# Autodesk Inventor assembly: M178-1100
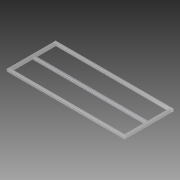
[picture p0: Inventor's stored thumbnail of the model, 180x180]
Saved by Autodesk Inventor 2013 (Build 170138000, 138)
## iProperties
Created: 2004-11
Part Number: M178-1100
Document SubType Name: Assembly
Designer: Autodesk, Inc.
Manufacturer: Standard
Standards Organization: Custom
Description: TABLE, TOP FRAM SUB ASSY
Mass: 12415.3 g
Surface Area: 32169.7 cm^2
Volume: 4521.81 cm^3
Density: 2.74564 g/cm^3
CAGE: 1LJX3
Dept. ID: Product Design
Description #2: ---
Finish #1: ---
Finish #2: ---
Material ID: ---
Project Number: ---
Author: Autodesk, Inc.
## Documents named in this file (6)
- Z:\_DATEN\Test Station\Components\M178-1100.iam
- Z:\_DATEN\Test Station\Components\M178-1002.ipt
- Z:\_DATEN\Test Station\Components\M178-1003.ipt
- Z:\_DATEN\Test Station\Components\20-004.iam
- Z:\_DATEN\Test Station\Components\M178-100_Cross_Phantom.iam
- C:\Users\kelleyb.ADS\Desktop\Samples MIGRATED 2009 224 RTM_1\Standard Parts\Test Station Content\Extrusions\40 Series Profiles.ipt
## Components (9 placed, 4 different names)
1. M178-1002:1
2. M178-1002:2
3. M178-1003:3 — Flush:8
4. M178-1003:4 — Mate:4, Flush:7
5. 20-004:1 [sub-assembly]
6. 20-004:2 [sub-assembly]
7. 20-004:3 [sub-assembly]
8. 20-004:4 [sub-assembly]
9. M178-100_Cross_Phantom:1 [sub-assembly] — Mate:4, Flush:7, Flush:8
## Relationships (3: Flush 2, Mate 1)
- Mate:4: M178-1003:4 ↔ M178-100_Cross_Phantom:1
- Flush:7: M178-1003:4 ↔ M178-100_Cross_Phantom:1
- Flush:8: M178-1003:3 ↔ M178-100_Cross_Phantom:1
## Named parameters: d3_d6 = 0, d4_d7 = 0, d5_d8 = 0, d7_d12 = 0, d8_d13 = 0, d9_d14 = 0, d10_d15 = 0, d13_d16 = 0
